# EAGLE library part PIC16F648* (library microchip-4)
MICROCONTROLLER PIC16F628(A) 16 I/O One 16-bit timer (TMR0) Two 8-bit timer (TMR0) Two comparators USART CCP/PWM Precision 4 MHz internal oscillator 4k Program Flash memory 256 bytes SRAM 256 bytes EEPROM
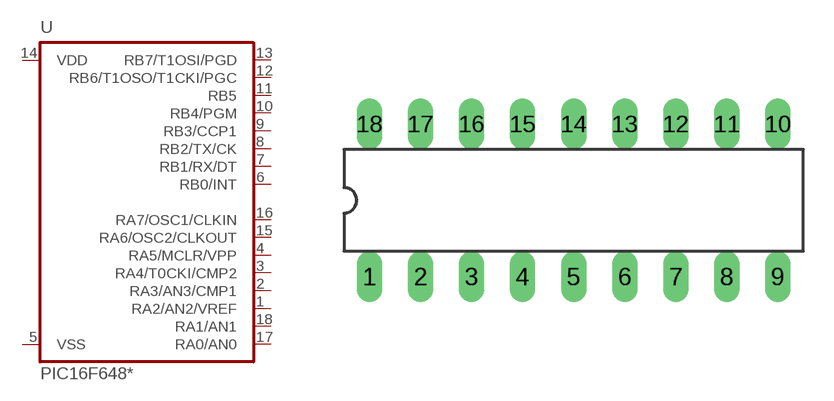
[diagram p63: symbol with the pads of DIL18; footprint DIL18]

Designator prefix -

## PIC16F648AI/P  [DIL18]
1  RA2/AN2/VREF
2  RA3/AN3/CMP1
3  RA4/T0CKI/CMP2
4  RA5/MCLR/VPP
5  VSS  pwr
6  RB0/INT
7  RB1/RX/DT
8  RB2/TX/CK
9  RB3/CCP1
10  RB4/PGM
11  RB5
12  RB6/T1OSO/T1CKI/PGC
13  RB7/T1OSI/PGD
14  VDD  pwr
15  RA6/OSC2/CLKOUT
16  RA7/OSC1/CLKIN
17  RA0/AN0
18  RA1/AN1

## PIC16F648I/P  [DIL18]
Pads as for DIL18

## Footprint DIL18 (pad centres in mm)
Dual In Line package type P
drill 0.5 pad 1.27 long: 1 -10.16,-3.81; 2 -7.62,-3.81; 3 -5.08,-3.81; 4 -2.54,-3.81; 5 0,-3.81; 6 2.54,-3.81; 7 5.08,-3.81; 8 7.62,-3.81; 9 10.16,-3.81; 10 10.16,3.81; 11 7.62,3.81; 12 5.08,3.81; 13 2.54,3.81; 14 0,3.81; 15 -2.54,3.81; 16 -5.08,3.81; 17 -7.62,3.81; 18 -10.16,3.81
